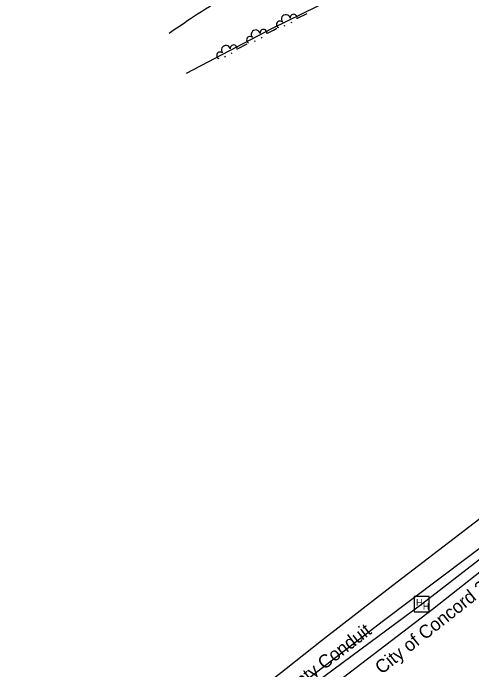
# Model space of a CAD drawing. Extents: x 1577032 to 1581865, y 611492 to 615011.
# Drawn here: x 1577790.1 to 1577963.2, y 612039.4 to 612287.4 of the extents above; entities that cross this region are included whole.
import ezdxf

# ---------------------------------------------------------------- set-up
doc = ezdxf.new("R2010")
doc.units = 0
for name, color, linetype in [('Exist Right of Way Line', 7, 'Continuous'), ('Exist Roads Soil', 7, 'Continuous'), ('Exist Utilities Telephone Hand Hole CELL', 7, 'Continuous'), ('Exist Utilities Telephone UG FO SUE LOS B', 7, 'Continuous'), ('Exist Utilities Telephone UG FO SUE LOS B Text', 7, 'Continuous'), ('Exist Utilities Water UG Line SUE LOS B', 7, 'Continuous'), ('Exist Utilities Water UG Line SUE LOS B Text', 7, 'Continuous'), ('Old_Level_11', 7, 'Continuous')]:
    doc.layers.add(name, color=color, linetype=linetype)

msp = doc.modelspace()

# ---------------------------------------------------------------- linework, layer by layer
at = {"layer": 'Exist Right of Way Line'}
msp.add_lwpolyline([(1577879.81, 612029.46), (1577893.14, 612039.99), (1577906.5, 612050.49), (1577919.89, 612060.95), (1577933.31, 612071.37), (1577946.76, 612081.75), (1577960.25, 612092.09), (1577973.76, 612102.39), (1577987.3, 612112.65), (1578000.88, 612122.88), (1578014.48, 612133.06), (1578028.12, 612143.2), (1578041.78, 612153.3), (1578055.47, 612163.36), (1578069.19, 612173.38), (1578082.95, 612183.36), (1578096.73, 612193.3), (1578110.54, 612203.2), (1578124.32, 612213.02)], dxfattribs=at)
at = {"layer": 'Exist Roads Soil'}
msp.add_spline([(1577849, 612279.91), (1577856.6, 612285.13), (1577868.73, 612292.76), (1577882.1, 612300.08), (1577898.85, 612310.11), (1577918.39, 612320.58), (1577940.76, 612330.77), (1577961.96, 612340.33), (1577983.92, 612350.63), (1578002.36, 612358.65), (1578027.59, 612372.04)], degree=3, dxfattribs=at)
at = {"layer": 'Exist Utilities Telephone Hand Hole CELL'}
for p, q in [((1577941.36, 612067.11), (1577941.36, 612061.38)), ((1577947.09, 612067.11), (1577941.36, 612067.11)), ((1577947.09, 612061.38), (1577947.09, 612067.11)), ((1577944.23, 612064.24), (1577944.23, 612064.24)), ((1577941.36, 612061.38), (1577947.09, 612061.38))]:
    msp.add_line(p, q, dxfattribs=at)
at = {"layer": 'Exist Utilities Telephone UG FO SUE LOS B'}
msp.add_lwpolyline([(1577891.4, 612025.03), (1577944.15, 612064.23), (1578009.21, 612114.6), (1578069.25, 612160.85), (1578124.61, 612197.76), (1578165.29, 612230.27), (1578195.73, 612250.34)], dxfattribs=at)
at = {"layer": 'Exist Utilities Water UG Line SUE LOS B'}
for p, q in [((1577948.39, 612062.4), (1578011.2, 612112.28)), ((1577893.72, 612020.67), (1577948.39, 612062.4))]:
    msp.add_line(p, q, dxfattribs=at)
at = {"layer": 'Old_Level_11'}
for points in [[(1577855.46, 612264.81), (1577887.96, 612281.79), (1577944.07, 612309.28)], [(1577897.38, 612285.49), (1577901.06, 612287.3)], [(1577894.98, 612283.86), (1577895.35, 612284.04)], [(1577886.01, 612279.85), (1577888.33, 612281.06), (1577889.64, 612281.71)], [(1577892.4, 612282.6), (1577892.77, 612282.78)], [(1577881.11, 612276.83), (1577881.47, 612277.02)], [(1577883.66, 612278.16), (1577884.02, 612278.35)], [(1577874.74, 612273.96), (1577878.38, 612275.86)], [(1577869.85, 612270.94), (1577870.21, 612271.13)], [(1577872.39, 612272.27), (1577872.75, 612272.46)], [(1578032.89, 612136.4), (1577972.55, 612090.14), (1577929.33, 612057.53), (1577881.07, 612020.31), (1577837.21, 611991.82), (1577791.97, 611949.22), (1577742.63, 611909.33), (1577722.94, 611892.08), (1577715.67, 611899.42), (1577703.6, 611913.37), (1577678.29, 611945.62), (1577656.31, 611970.48), (1577655.04, 611981.23), (1577659.19, 611990.63), (1577657.65, 611999.5), (1577644.83, 612008.29), (1577631.44, 612018.02), (1577616.7, 612031.35), (1577598.74, 612051.52), (1577590.87, 612064.53)]]:
    msp.add_lwpolyline(points, dxfattribs=at)
for centre, radius, start, end in [((1577892.97, 612285.16), 1.69, 12.0616, 220.1341), ((1577895.91, 612285.69), 1.3, 346.8664, 187.6629), ((1577890.75, 612283.16), 1.3, 44.5328, 245.3294), ((1577881.62, 612279.4), 1.69, 13.5583, 221.6308), ((1577884.54, 612280.01), 1.3, 348.363, 189.1596), ((1577879.45, 612277.35), 1.3, 46.0295, 246.8261), ((1577870.35, 612273.52), 1.69, 13.5583, 221.6308), ((1577873.27, 612274.12), 1.3, 348.363, 189.1596), ((1577868.18, 612271.46), 1.3, 46.0295, 246.8261)]:
    msp.add_arc(centre, radius, start, end, dxfattribs=at)

# ---------------------------------------------------------------- texts
at = {"layer": 'Exist Utilities Telephone Hand Hole CELL'}
for p in [(1577942.14, 612063.65), (1577944.71, 612062.19)]:
    msp.add_text('H', height=2.5, dxfattribs=at).set_placement(p)
at = {"layer": 'Exist Utilities Telephone UG FO SUE LOS B Text'}
msp.add_text('Empty Conduit', height=5, rotation=37.6596, dxfattribs=at).set_placement((1577890.97, 612026.55))
at = {"layer": 'Exist Utilities Water UG Line SUE LOS B Text'}
msp.add_text('City of Concord 30" DIP', height=5, rotation=38.4541, dxfattribs=at).set_placement((1577929.13, 612037.53))

doc.saveas('drawing.dxf')
